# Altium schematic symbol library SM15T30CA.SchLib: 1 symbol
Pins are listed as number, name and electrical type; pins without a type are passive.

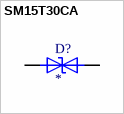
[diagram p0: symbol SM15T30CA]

## SM15T30CA
designator D?
1500 W, 25.6 V TVS; MF: ON Semiconductor; MP: SMCJ70CA
footprint SM15T30CA
pins: 1, 2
